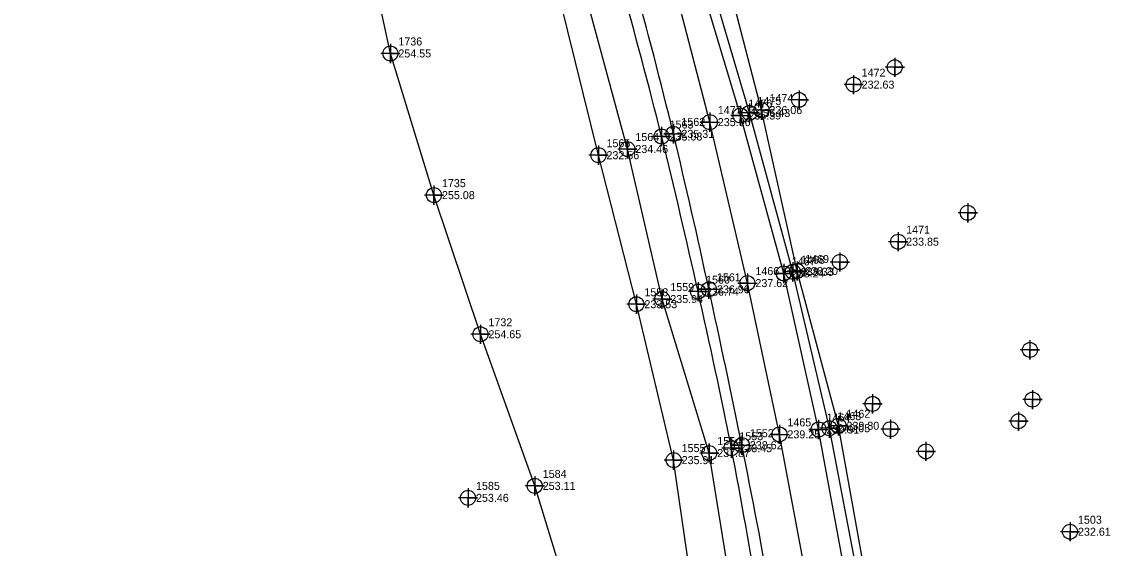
# Model space of a CAD drawing. Extents: x 2130962 to 2131465, y 643052 to 644206.
# Drawn here: x 2130964.8 to 2131304.7, y 643631.2 to 643795.8 of the extents above; entities that cross this region are included whole.
import ezdxf

# ---------------------------------------------------------------- set-up
doc = ezdxf.new("R2010")
doc.units = 0
for name, color, linetype in [('Exist DTM Breakline', 7, 'Continuous'), ('Exist DTM Breakline Cogo Elevation', 7, 'Continuous'), ('Exist DTM Breakline Cogo Number', 7, 'Continuous'), ('Exist DTM Breakline Cogo Point CELL', 7, 'Continuous'), ('Exist DTM Drainline', 7, 'Continuous'), ('Exist DTM Drainline Cogo Elevation', 7, 'Continuous'), ('Exist DTM Drainline Cogo Number', 7, 'Continuous'), ('Exist DTM Drainline Cogo Point CELL', 7, 'Continuous'), ('Exist DTM Regular Point CELL', 7, 'Continuous'), ('Exist DTM Regular Point Cogo Elevation', 7, 'Continuous'), ('Exist DTM Regular Point Cogo Number', 7, 'Continuous'), ('Exist Roads EOP', 7, 'Continuous'), ('Exist Roads EOP Cogo Elevation', 7, 'Continuous'), ('Exist Roads EOP Cogo Number', 7, 'Continuous'), ('Exist Roads EOP Cogo Point CELL', 7, 'Continuous'), ('Exist Roads EOT', 7, 'Continuous'), ('Exist Roads EOT Cogo Elevation', 7, 'Continuous'), ('Exist Roads EOT Cogo Number', 7, 'Continuous'), ('Exist Roads EOT Cogo Point CELL', 7, 'Continuous'), ('Exist Roads Soil', 7, 'Continuous'), ('Exist Roads Soil Cogo Elevation', 7, 'Continuous'), ('Exist Roads Soil Cogo Number', 7, 'Continuous'), ('Exist Roads Soil Cogo Point CELL', 7, 'Continuous')]:
    doc.layers.add(name, color=color, linetype=linetype)

msp = doc.modelspace()

# ---------------------------------------------------------------- linework, layer by layer
at = {"layer": 'Exist DTM Breakline'}
for points in [[(2131139.0887, 643604.6918), (2131124.996, 643650.6897), (2131108.0385, 643698.079), (2131093.5223, 643741.563), (2131079.9108, 643785.8518), (2131069.3516, 643834.7964), (2131058.0914, 643882.3322), (2131042.317, 643929.1682), (2131027.5453, 643975.0277), (2131014.156, 644017.233), (2130995.2084, 644066.2506), (2130976.662, 644110.4992), (2130964.7831, 644158.2254)], [(2131266.3306, 643269.372), (2131264.0776, 643319.4437), (2131258.8396, 643369.5498), (2131255.3671, 643419.5794), (2131249.6414, 643469.556), (2131244.7652, 643520.0623), (2131238.8778, 643569.4077), (2131228.6495, 643620.6699), (2131219.85, 643669.4823), (2131206.9682, 643717.8453), (2131195.8132, 643768.1497), (2131183.2404, 643816.8151), (2131169.0496, 643865.1461), (2131151.2314, 643913.4424), (2131130.7295, 643958.9736), (2131122.7411, 643983.0115)]]:
    msp.add_lwpolyline(points, dxfattribs=at)
at = {"layer": 'Exist DTM Breakline Cogo Point CELL'}
for points in [[(2131079.9108, 643788.8518), (2131079.9108, 643782.8518), (2131079.9108, 643785.8518), (2131082.9108, 643785.8518), (2131076.9108, 643785.8518)], [(2131195.8132, 643771.1497), (2131195.8132, 643765.1497), (2131195.8132, 643768.1497), (2131198.8132, 643768.1497), (2131192.8132, 643768.1497)], [(2131093.5223, 643744.563), (2131093.5223, 643738.563), (2131093.5223, 643741.563), (2131096.5223, 643741.563), (2131090.5223, 643741.563)], [(2131206.9682, 643720.8453), (2131206.9682, 643714.8453), (2131206.9682, 643717.8453), (2131209.9682, 643717.8453), (2131203.9682, 643717.8453)], [(2131108.0385, 643701.079), (2131108.0385, 643695.079), (2131108.0385, 643698.079), (2131111.0385, 643698.079), (2131105.0385, 643698.079)], [(2131219.85, 643672.4823), (2131219.85, 643666.4823), (2131219.85, 643669.4823), (2131222.85, 643669.4823), (2131216.85, 643669.4823)], [(2131124.996, 643653.6897), (2131124.996, 643647.6897), (2131124.996, 643650.6897), (2131127.996, 643650.6897), (2131121.996, 643650.6897)]]:
    msp.add_lwpolyline(points, dxfattribs=at)
for centre in [(2131079.9108, 643785.8518), (2131195.8132, 643768.1497), (2131093.5223, 643741.563), (2131206.9682, 643717.8453), (2131108.0385, 643698.079), (2131219.85, 643669.4823), (2131124.996, 643650.6897)]:
    msp.add_circle(centre, 2.344, dxfattribs=at)
at = {"layer": 'Exist DTM Drainline'}
msp.add_lwpolyline([(2131000.2029, 643226.7228), (2131050.9884, 643228.9032), (2131099.0297, 643228.5605), (2131120.2968, 643239.3591), (2131144.9156, 643253.3469), (2131146.4739, 643252.3674), (2131154.3188, 643256.8046), (2131168.9618, 643265.5132), (2131176.6257, 643272.964), (2131179.8144, 643285.303), (2131183.3842, 643315.022), (2131190.1471, 643365.8731), (2131190.1489, 643413.686), (2131192.3886, 643466.4632), (2131188.8083, 643512.615), (2131184.0059, 643563.7066), (2131175.3, 643610.7482), (2131168.3784, 643658.7431), (2131156.7476, 643707.4708), (2131144.9036, 643754.0458), (2131132.9438, 643802.544), (2131118.0831, 643847.9475), (2131104.0084, 643896.8663), (2131096.3866, 643919.4077)], dxfattribs=at)
at = {"layer": 'Exist DTM Drainline Cogo Point CELL'}
for points in [[(2131144.9036, 643757.0458), (2131144.9036, 643751.0458), (2131144.9036, 643754.0458), (2131147.9036, 643754.0458), (2131141.9036, 643754.0458)], [(2131156.7476, 643710.4708), (2131156.7476, 643704.4708), (2131156.7476, 643707.4708), (2131159.7476, 643707.4708), (2131153.7476, 643707.4708)], [(2131168.3784, 643661.7431), (2131168.3784, 643655.7431), (2131168.3784, 643658.7431), (2131171.3784, 643658.7431), (2131165.3784, 643658.7431)]]:
    msp.add_lwpolyline(points, dxfattribs=at)
for centre in [(2131144.9036, 643754.0458), (2131156.7476, 643707.4708), (2131168.3784, 643658.7431)]:
    msp.add_circle(centre, 2.344, dxfattribs=at)
at = {"layer": 'Exist DTM Regular Point CELL'}
for points in [[(2131237.4311, 643784.5173), (2131237.4311, 643778.5173), (2131237.4311, 643781.5173), (2131240.4311, 643781.5173), (2131234.4311, 643781.5173)], [(2131224.5926, 643779.1069), (2131224.5926, 643773.1069), (2131224.5926, 643776.1069), (2131227.5926, 643776.1069), (2131221.5926, 643776.1069)], [(2131207.5376, 643774.3105), (2131207.5376, 643768.3105), (2131207.5376, 643771.3105), (2131210.5376, 643771.3105), (2131204.5376, 643771.3105)], [(2131260.2454, 643739.0495), (2131260.2454, 643733.0495), (2131260.2454, 643736.0495), (2131263.2454, 643736.0495), (2131257.2454, 643736.0495)], [(2131238.5038, 643730.0137), (2131238.5038, 643724.0137), (2131238.5038, 643727.0137), (2131241.5038, 643727.0137), (2131235.5038, 643727.0137)], [(2131220.288, 643723.6674), (2131220.288, 643717.6674), (2131220.288, 643720.6674), (2131223.288, 643720.6674), (2131217.288, 643720.6674)], [(2131279.6508, 643696.1856), (2131279.6508, 643690.1856), (2131279.6508, 643693.1856), (2131282.6508, 643693.1856), (2131276.6508, 643693.1856)], [(2131280.4447, 643680.6519), (2131280.4447, 643674.6519), (2131280.4447, 643677.6519), (2131283.4447, 643677.6519), (2131277.4447, 643677.6519)], [(2131230.5131, 643679.3182), (2131230.5131, 643673.3182), (2131230.5131, 643676.3182), (2131233.5131, 643676.3182), (2131227.5131, 643676.3182)], [(2131276.0697, 643673.8706), (2131276.0697, 643667.8706), (2131276.0697, 643670.8706), (2131279.0697, 643670.8706), (2131273.0697, 643670.8706)], [(2131236.1124, 643671.4152), (2131236.1124, 643665.4152), (2131236.1124, 643668.4152), (2131239.1124, 643668.4152), (2131233.1124, 643668.4152)], [(2131247.149, 643664.4846), (2131247.149, 643658.4846), (2131247.149, 643661.4846), (2131250.149, 643661.4846), (2131244.149, 643661.4846)], [(2131104.1546, 643649.9473), (2131104.1546, 643643.9473), (2131104.1546, 643646.9473), (2131107.1546, 643646.9473), (2131101.1546, 643646.9473)], [(2131292.1683, 643639.3612), (2131292.1683, 643633.3612), (2131292.1683, 643636.3612), (2131295.1683, 643636.3612), (2131289.1683, 643636.3612)]]:
    msp.add_lwpolyline(points, dxfattribs=at)
for centre in [(2131237.4311, 643781.5173), (2131224.5926, 643776.1069), (2131207.5376, 643771.3105), (2131260.2454, 643736.0495), (2131238.5038, 643727.0137), (2131220.288, 643720.6674), (2131279.6508, 643693.1856), (2131280.4447, 643677.6519), (2131230.5131, 643676.3182), (2131276.0697, 643670.8706), (2131236.1124, 643668.4152), (2131247.149, 643661.4846), (2131104.1546, 643646.9473), (2131292.1683, 643636.3612)]:
    msp.add_circle(centre, 2.344, dxfattribs=at)
at = {"layer": 'Exist Roads EOP'}
msp.add_lwpolyline([(2131264.2715, 643222.5647), (2131259.8757, 643269.3254), (2131257.0196, 643319.4043), (2131254.2561, 643369.6499), (2131250.0777, 643419.4187), (2131246.1511, 643469.0294), (2131240.8382, 643519.1271), (2131234.3674, 643568.5584), (2131226.3321, 643620.1808), (2131217.0271, 643668.7116), (2131205.6213, 643717.607), (2131192.0578, 643767.2595), (2131177.9714, 643815.0911), (2131162.2913, 643862.9344), (2131145.3604, 643910.8486), (2131126.9113, 643957.2915), (2131112.3691, 643996.1228)], dxfattribs=at)
msp.add_spline([(2131166.2495, 643216.6951), (2131171.8131, 643218.7244), (2131182.3713, 643223.9726), (2131191.8117, 643231.1489), (2131200.5013, 643239.6993), (2131208.8071, 643249.0697), (2131216.0672, 643259.0032), (2131218.7188, 643264.347), (2131220.5363, 643270.0958), (2131222.8445, 643282.0077), (2131224.3583, 643293.9245), (2131224.8763, 643317.7904), (2131222.0632, 643367.6716), (2131218.5448, 643416.8114), (2131214.3187, 643466.3462), (2131209.1735, 643515.6666), (2131202.7939, 643565.1545), (2131195.0475, 643613.9937), (2131186.4014, 643662.4763), (2131176.0113, 643711.405), (2131164.6154, 643759.8896), (2131151.874, 643807.8526), (2131137.8554, 643855.4065), (2131122.5733, 643902.8574), (2131105.9622, 643949.4862), (2131091.5349, 643988.0437)], degree=3, dxfattribs=at)
at = {"layer": 'Exist Roads EOP Cogo Point CELL'}
for points in [[(2131192.0578, 643770.2595), (2131192.0578, 643764.2595), (2131192.0578, 643767.2595), (2131195.0578, 643767.2595), (2131189.0578, 643767.2595)], [(2131164.6154, 643762.8896), (2131164.6154, 643756.8896), (2131164.6154, 643759.8896), (2131167.6154, 643759.8896), (2131161.6154, 643759.8896)], [(2131205.6213, 643720.607), (2131205.6213, 643714.607), (2131205.6213, 643717.607), (2131208.6213, 643717.607), (2131202.6213, 643717.607)], [(2131176.0113, 643714.405), (2131176.0113, 643708.405), (2131176.0113, 643711.405), (2131179.0113, 643711.405), (2131173.0113, 643711.405)], [(2131217.0271, 643671.7116), (2131217.0271, 643665.7116), (2131217.0271, 643668.7116), (2131220.0271, 643668.7116), (2131214.0271, 643668.7116)], [(2131186.4014, 643665.4763), (2131186.4014, 643659.4763), (2131186.4014, 643662.4763), (2131189.4014, 643662.4763), (2131183.4014, 643662.4763)]]:
    msp.add_lwpolyline(points, dxfattribs=at)
for centre in [(2131192.0578, 643767.2595), (2131164.6154, 643759.8896), (2131205.6213, 643717.607), (2131176.0113, 643711.405), (2131217.0271, 643668.7116), (2131186.4014, 643662.4763)]:
    msp.add_circle(centre, 2.344, dxfattribs=at)
at = {"layer": 'Exist Roads EOT'}
for points in [[(2131255.7894, 643269.2666), (2131252.7511, 643319.2443), (2131249.9083, 643369.5477), (2131246.3502, 643419.1778), (2131242.1933, 643468.6938), (2131237.0867, 643518.9193), (2131230.8671, 643568.2588), (2131222.7066, 643619.1047), (2131213.6442, 643668.3078), (2131202.755, 643717.0933), (2131189.234, 643766.4577), (2131174.9499, 643814.1787), (2131159.2111, 643861.933), (2131141.9103, 643909.6722), (2131123.7008, 643956.0828), (2131104.9436, 644003.1503), (2131086.2706, 644048.8072), (2131065.6997, 644094.9191), (2131044.3618, 644140.0645), (2131021.6804, 644185.4526)], [(2131237.6994, 643363.706), (2131234.1644, 643418.0043), (2131229.8934, 643468.0098), (2131225.1139, 643518.3873), (2131218.7748, 643566.6133), (2131210.7043, 643617.3811), (2131201.4139, 643666.7928), (2131191.4121, 643714.0755), (2131179.6696, 643764.3904), (2131167.3006, 643812.1237), (2131153.7359, 643860.4033), (2131138.3711, 643908.8544), (2131125.1607, 643951.4161)]]:
    msp.add_lwpolyline(points, dxfattribs=at)
msp.add_spline([(2131166.718, 643215.2083), (2131172.3866, 643217.1804), (2131211.4056, 643247.1499), (2131223.758, 643268.7314), (2131228.3848, 643317.935), (2131225.533, 643367.8628), (2131222.2486, 643417.1873), (2131217.9619, 643466.6275), (2131212.8794, 643516.2377), (2131206.5633, 643565.5764), (2131198.9021, 643614.6757), (2131189.6851, 643663.4055), (2131179.3985, 643712.1311), (2131168.3085, 643760.7185), (2131155.755, 643808.9129), (2131141.6748, 643856.5528), (2131126.5354, 643904.2758), (2131110.3559, 643951.0191), (2131092.4533, 643998.1348), (2131073.722, 644043.631), (2131053.1654, 644089.359), (2131032.0052, 644134.0908), (2131009.0644, 644179.3802)], degree=3, dxfattribs=at)
at = {"layer": 'Exist Roads EOT Cogo Point CELL'}
for points in [[(2131189.234, 643769.4577), (2131189.234, 643763.4577), (2131189.234, 643766.4577), (2131186.234, 643766.4577), (2131192.234, 643766.4577)], [(2131179.6696, 643767.3904), (2131179.6696, 643761.3904), (2131179.6696, 643764.3904), (2131176.6696, 643764.3904), (2131182.6696, 643764.3904)], [(2131168.3085, 643763.7185), (2131168.3085, 643757.7185), (2131168.3085, 643760.7185), (2131165.3085, 643760.7185), (2131171.3085, 643760.7185)], [(2131191.4121, 643717.0755), (2131191.4121, 643711.0755), (2131191.4121, 643714.0755), (2131188.4121, 643714.0755), (2131194.4121, 643714.0755)], [(2131202.755, 643720.0933), (2131202.755, 643714.0933), (2131202.755, 643717.0933), (2131199.755, 643717.0933), (2131205.755, 643717.0933)], [(2131179.3985, 643715.1311), (2131179.3985, 643709.1311), (2131179.3985, 643712.1311), (2131176.3985, 643712.1311), (2131182.3985, 643712.1311)], [(2131201.4139, 643669.7928), (2131201.4139, 643663.7928), (2131201.4139, 643666.7928), (2131198.4139, 643666.7928), (2131204.4139, 643666.7928)], [(2131213.6442, 643671.3078), (2131213.6442, 643665.3078), (2131213.6442, 643668.3078), (2131210.6442, 643668.3078), (2131216.6442, 643668.3078)], [(2131189.6851, 643666.4055), (2131189.6851, 643660.4055), (2131189.6851, 643663.4055), (2131186.6851, 643663.4055), (2131192.6851, 643663.4055)]]:
    msp.add_lwpolyline(points, dxfattribs=at)
for centre in [(2131189.234, 643766.4577), (2131179.6696, 643764.3904), (2131168.3085, 643760.7185), (2131202.755, 643717.0933), (2131179.3985, 643712.1311), (2131191.4121, 643714.0755), (2131213.6442, 643668.3078), (2131201.4139, 643666.7928), (2131189.6851, 643663.4055)]:
    msp.add_circle(centre, 2.344, dxfattribs=at)
at = {"layer": 'Exist Roads Soil'}
msp.add_lwpolyline([(2131224.8674, 643317.753), (2131220.141, 643317.6487), (2131216.7544, 643367.544), (2131211.084, 643416.163), (2131207.4344, 643466.363), (2131202.1097, 643514.7948), (2131195.0195, 643564.3052), (2131187.2605, 643612.6498), (2131179.506, 643660.9545), (2131164.8317, 643709.0781), (2131153.9175, 643755.9834), (2131140.8896, 643804.492), (2131127.2512, 643851.9231), (2131113.4771, 643899.8082), (2131083.6685, 643994.997), (2131066.191, 644040.9476), (2131049.1539, 644087.3869)], dxfattribs=at)
at = {"layer": 'Exist Roads Soil Cogo Point CELL'}
for points in [[(2131153.9175, 643752.9834), (2131153.9175, 643758.9834), (2131153.9175, 643755.9834), (2131156.9175, 643755.9834), (2131150.9175, 643755.9834)], [(2131164.8317, 643706.0781), (2131164.8317, 643712.0781), (2131164.8317, 643709.0781), (2131167.8317, 643709.0781), (2131161.8317, 643709.0781)], [(2131179.506, 643657.9545), (2131179.506, 643663.9545), (2131179.506, 643660.9545), (2131182.506, 643660.9545), (2131176.506, 643660.9545)]]:
    msp.add_lwpolyline(points, dxfattribs=at)
for centre in [(2131153.9175, 643755.9834), (2131164.8317, 643709.0781), (2131179.506, 643660.9545)]:
    msp.add_circle(centre, 2.344, dxfattribs=at)

# ---------------------------------------------------------------- texts
at = {"layer": 'Exist DTM Breakline Cogo Elevation'}
for s, p in [('254.55', (2131082.4108, 643784.6018)), ('236.06', (2131198.3132, 643766.8997)), ('255.08', (2131096.0223, 643740.313)), ('238.20', (2131209.4682, 643716.5953)), ('254.65', (2131110.5385, 643696.829)), ('239.80', (2131222.35, 643668.2323)), ('253.11', (2131127.496, 643649.4397))]:
    msp.add_text(s, height=2.5, dxfattribs=at).set_placement(p)
at = {"layer": 'Exist DTM Breakline Cogo Number'}
for s, p in [('1736', (2131082.4108, 643788.3518)), ('1474', (2131198.3132, 643770.6497)), ('1735', (2131096.0223, 643744.063)), ('1469', (2131209.4682, 643720.3453)), ('1732', (2131110.5385, 643700.579)), ('1462', (2131222.35, 643671.9823)), ('1584', (2131127.496, 643653.1897))]:
    msp.add_text(s, height=2.5, dxfattribs=at).set_placement(p)
at = {"layer": 'Exist DTM Drainline Cogo Elevation'}
for s, p in [('232.56', (2131147.4036, 643752.7958)), ('233.53', (2131159.2476, 643706.2208)), ('235.91', (2131170.8784, 643657.4931))]:
    msp.add_text(s, height=2.5, dxfattribs=at).set_placement(p)
at = {"layer": 'Exist DTM Drainline Cogo Number'}
for s, p in [('1565', (2131147.4036, 643756.5458)), ('1558', (2131159.2476, 643709.9708)), ('1555', (2131170.8784, 643661.2431))]:
    msp.add_text(s, height=2.5, dxfattribs=at).set_placement(p)
at = {"layer": 'Exist DTM Regular Point Cogo Elevation'}
for s, p in [('232.63', (2131227.0926, 643774.8569)), ('233.85', (2131241.0038, 643725.7637)), ('253.46', (2131106.6546, 643645.6973)), ('232.61', (2131294.6683, 643635.1112))]:
    msp.add_text(s, height=2.5, dxfattribs=at).set_placement(p)
at = {"layer": 'Exist DTM Regular Point Cogo Number'}
for s, p in [('1472', (2131227.0926, 643778.6069)), ('1471', (2131241.0038, 643729.5137)), ('1585', (2131106.6546, 643649.4473)), ('1503', (2131294.6683, 643638.8612))]:
    msp.add_text(s, height=2.5, dxfattribs=at).set_placement(p)
at = {"layer": 'Exist Roads EOP Cogo Elevation'}
for s, p in [('236.43', (2131194.5578, 643766.0095)), ('235.08', (2131167.1154, 643758.6396)), ('238.33', (2131208.1213, 643716.357)), ('236.74', (2131178.5113, 643710.155)), ('240.05', (2131219.5271, 643667.4616)), ('238.45', (2131188.9014, 643661.2263))]:
    msp.add_text(s, height=2.5, dxfattribs=at).set_placement(p)
at = {"layer": 'Exist Roads EOP Cogo Number'}
for s, p in [('1475', (2131194.5578, 643769.7595)), ('1563', (2131167.1154, 643762.3896)), ('1468', (2131208.1213, 643720.107)), ('1560', (2131178.5113, 643713.905)), ('1463', (2131219.5271, 643671.2116)), ('1553', (2131188.9014, 643664.9763))]:
    msp.add_text(s, height=2.5, dxfattribs=at).set_placement(p)
at = {"layer": 'Exist Roads EOT Cogo Elevation'}
for s, p in [('235.96', (2131182.1696, 643763.1404)), ('236.39', (2131191.734, 643765.2077)), ('235.31', (2131170.8085, 643759.4685)), ('238.24', (2131205.255, 643715.8433)), ('237.62', (2131193.9121, 643712.8255)), ('236.96', (2131181.8985, 643710.8811)), ('239.91', (2131216.1442, 643667.0578)), ('239.25', (2131203.9139, 643665.5428)), ('238.62', (2131192.1851, 643662.1555))]:
    msp.add_text(s, height=2.5, dxfattribs=at).set_placement(p)
at = {"layer": 'Exist Roads EOT Cogo Number'}
for s, p in [('1476', (2131191.734, 643768.9577)), ('1477', (2131182.1696, 643766.8904)), ('1562', (2131170.8085, 643763.2185)), ('1467', (2131205.255, 643719.5933)), ('1561', (2131181.8985, 643714.6311)), ('1466', (2131193.9121, 643716.5755)), ('1464', (2131216.1442, 643670.8078)), ('1465', (2131203.9139, 643669.2928)), ('1552', (2131192.1851, 643665.9055))]:
    msp.add_text(s, height=2.5, dxfattribs=at).set_placement(p)
at = {"layer": 'Exist Roads Soil Cogo Elevation'}
for s, p in [('234.46', (2131156.4175, 643754.7334)), ('235.94', (2131167.3317, 643707.8281)), ('237.87', (2131182.006, 643659.7045))]:
    msp.add_text(s, height=2.5, dxfattribs=at).set_placement(p)
at = {"layer": 'Exist Roads Soil Cogo Number'}
for s, p in [('1564', (2131156.4175, 643758.4834)), ('1559', (2131167.3317, 643711.5781)), ('1554', (2131182.006, 643663.4545))]:
    msp.add_text(s, height=2.5, dxfattribs=at).set_placement(p)

doc.saveas('drawing.dxf')
